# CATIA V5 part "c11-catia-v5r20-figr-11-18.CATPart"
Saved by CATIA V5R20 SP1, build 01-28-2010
Part number: Part1
Bounding box of the stored display mesh (mm): x -89.703 to 75.958, y -127.286 to 108.862, z -26.487 to 19.815
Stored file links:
  D:\v5_r20\psrt_files_downloaded\c11\c11-catia-v5r20-figr-11-18.CATPart
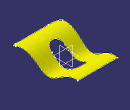
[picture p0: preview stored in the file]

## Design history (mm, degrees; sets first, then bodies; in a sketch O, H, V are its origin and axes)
Set1
  Extrude1: Element1 Sketch3, Lim1 86, Lim2 94, Direction yz-plane
  Sketch1 on xy-plane, origin (0, 0, 0), H (1, 0, 0), V (0, 1, 0)
    line L1 (64.3059, 108.8616) -> (75.9293, -106.0218)
    arc A1 centre (55.7837, -107.1115) radius 20.175 from (75.9293, -106.0218) to (55.7837, -127.2865) cw
    line L2 (55.7837, -127.2865) -> (-64.7868, -127.2865)
    arc A2 centre (-64.7868, -102.3613) radius 24.9252 from (-64.7868, -127.2865) to (-89.6873, -101.2501) cw
    line L3 (-89.6873, -101.2501) -> (-80.3115, 108.8616)
    line L4 (-80.3115, 108.8616) -> (64.3059, 108.8616)
    tangency: A1 L1, A2 L2, A2 L3, A1 L2
    horizontal: L2 H, L4 H
  Extrude2: Element1 Sketch1, Lim1 86, Lim2 94, Direction xy-plane
  Split1: ToCut Extrude1, Cutting Extrude2
  Sketch2 on xy-plane, origin (0, 0, 0), H (1, 0, 0), V (0, 1, 0)
    construction line L1 (-11.3849, 28.4134) -> (-11.3849, -36.9379)
    line L2 (12.8382, 28.4134) -> (12.8382, -36.9379)
    line L3 (-35.608, -36.9379) -> (-35.608, 28.4134)
    arc A1 centre (-11.3849, -36.9379) radius 24.2231 from (12.8382, -36.9379) to (-35.608, -36.9379) cw
    arc A2 centre (-11.3849, 28.4134) radius 24.2231 from (-35.608, 28.4134) to (12.8382, 28.4134) cw
    vertical: L1 V
    tangency: A1 L2, A2 L2, A1 L3, A2 L3
    parallelism: L1 L2
  Extrude3: Element1 Sketch2, Lim1 86, Lim2 94, Direction xy-plane
  Split2: ToCut Split1, Cutting Extrude3
  Boundary1: Boundary edge of Split2, Support Split2
Body1 (main body)
  Sketch3 on yz-plane, origin (0, 0, 0), H (0, 1, 0), V (0, 0, 1)
    spline S1 through (-130.9721, 0) (-85.5087, 19.8151) (-38.0512, 0) (0, -25.6483) (60.0541, -1.7202) (134.7951, -4.3868)
    point P1 (-130.9721, 0)
    point P2 (-38.0512, 0)
    point P3 (0, -25.6483)
    coincidence: P1 H, P2 H, P3 V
